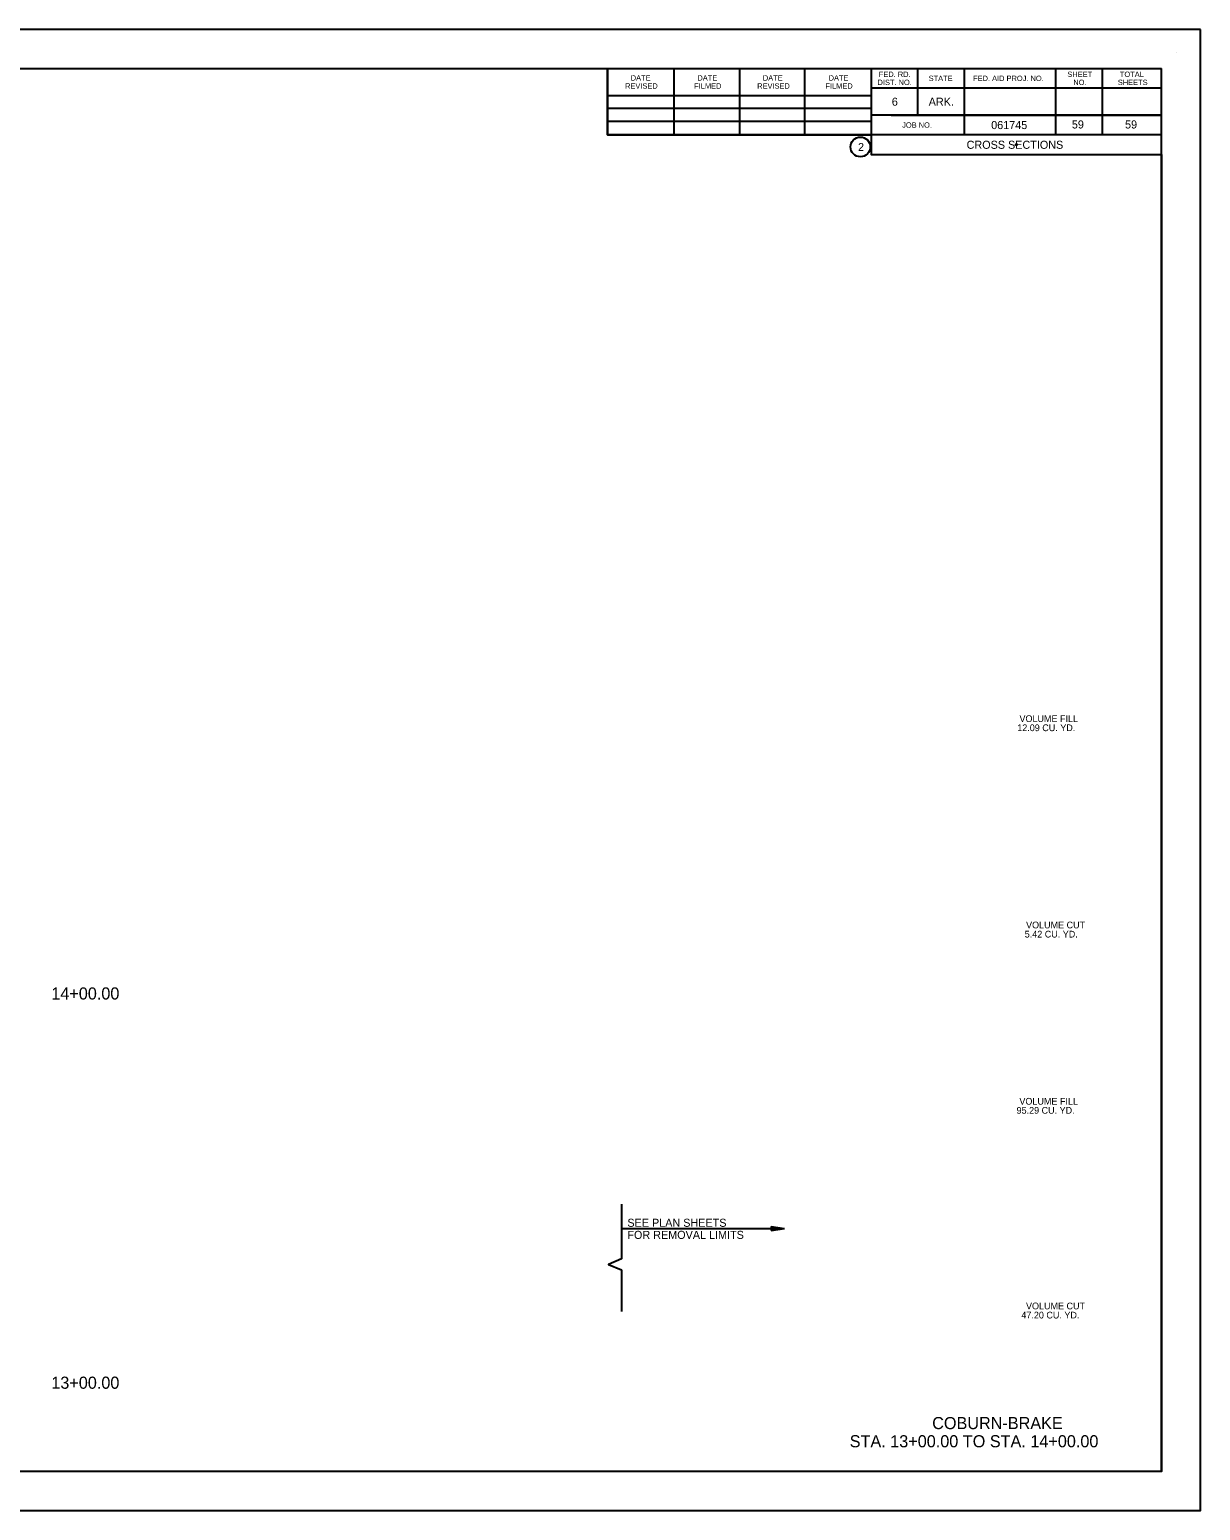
# Model space of a CAD drawing. Extents: x 1284907 to 1285667, y 403630 to 403851.
# Drawn here: x 1285493.5 to 1285667.4, y 403630.2 to 403850.2 of the extents above; entities that cross this region are included whole.
import ezdxf

# ---------------------------------------------------------------- set-up
doc = ezdxf.new("R2010")
doc.units = 0
for name, color, linetype in [('1', 7, 'Continuous'), ('Default', 7, 'Continuous'), ('NO PLOT CELL', 7, 'Continuous'), ('R_Draft', 7, 'Continuous'), ('R_Grid_Sta', 7, 'Continuous'), ('R_Vert Alg Annot_Drive', 7, 'Continuous')]:
    doc.layers.add(name, color=color, linetype=linetype)

msp = doc.modelspace()

# ---------------------------------------------------------------- linework, layer by layer
at = {"layer": '1'}
for p, q in [((1285663.82, 403846.78), (1285663.82, 403846.78)), ((1285342.56, 403844.47), (1285661.63, 403844.47)), ((1285579.37, 403834.59), (1285579.37, 403844.47)), ((1285589.23, 403834.59), (1285589.23, 403844.27)), ((1285598.99, 403834.59), (1285598.99, 403844.27)), ((1285608.67, 403834.59), (1285608.67, 403844.27)), ((1285618.53, 403844.47), (1285618.53, 403831.67)), ((1285625.37, 403844.47), (1285625.37, 403837.53)), ((1285632.31, 403844.47), (1285632.31, 403834.59)), ((1285645.89, 403844.47), (1285645.89, 403834.59)), ((1285652.83, 403844.47), (1285652.83, 403834.59)), ((1285661.63, 403636.01), (1285661.63, 403844.47)), ((1285661.63, 403841.53), (1285618.53, 403841.53)), ((1285661.63, 403841.55), (1285661.63, 403841.55)), ((1285579.37, 403840.45), (1285618.53, 403840.45)), ((1285579.37, 403838.59), (1285618.53, 403838.59)), ((1285579.37, 403834.59), (1285579.37, 403836.65)), ((1285579.37, 403836.65), (1285618.53, 403836.65)), ((1285661.63, 403837.53), (1285618.53, 403837.53)), ((1285621.49, 403837.53), (1285661.63, 403837.53)), ((1285661.63, 403834.59), (1285579.37, 403834.59)), ((1285618.53, 403831.67), (1285661.63, 403831.67)), ((1285661.63, 403636.01), (1285342.56, 403636.01))]:
    msp.add_line(p, q, dxfattribs=at)
for points in [[(1285667.4, 403850.24), (1285327.4, 403850.24), (1285327.4, 403630.24), (1285667.4, 403630.24)], [(1285342.56, 403636.01), (1285342.56, 403844.47), (1285579.37, 403844.47), (1285579.37, 403834.59), (1285618.53, 403834.59), (1285618.53, 403831.67), (1285661.63, 403831.67), (1285661.63, 403636.01)]]:
    msp.add_lwpolyline(points, close=True, dxfattribs=at)
msp.add_circle((1285616.91, 403832.81), 1.47, dxfattribs=at)
at = {"layer": 'NO PLOT CELL'}
msp.add_circle((1285640.08, 403833.13), 0.1, dxfattribs=at)
at = {"layer": 'R_Draft'}
for p, q in [((1285603.64, 403672.44), (1285605.64, 403672.14)), ((1285603.64, 403672.44), (1285603.64, 403671.84)), ((1285603.64, 403672.39), (1285605.31, 403672.14)), ((1285603.64, 403672.34), (1285604.96, 403672.14)), ((1285603.64, 403672.29), (1285604.63, 403672.14)), ((1285603.64, 403672.24), (1285604.29, 403672.14)), ((1285603.64, 403672.19), (1285603.96, 403672.14)), ((1285603.64, 403671.84), (1285605.64, 403672.14)), ((1285603.64, 403672.04), (1285604.29, 403672.14)), ((1285603.64, 403671.94), (1285604.96, 403672.14)), ((1285603.64, 403671.89), (1285605.31, 403672.14)), ((1285603.64, 403671.99), (1285604.63, 403672.14)), ((1285603.64, 403672.1), (1285603.96, 403672.14)), ((1285581.43, 403665.98), (1285581.43, 403659.78))]:
    msp.add_line(p, q, dxfattribs=at)
msp.add_lwpolyline([(1285581.43, 403675.74), (1285581.43, 403667.6), (1285579.52, 403666.76), (1285581.43, 403665.98)], dxfattribs=at)
at = {"layer": 'R_Vert Alg Annot_Drive'}
msp.add_line((1285581.43, 403672.14), (1285605.64, 403672.14), dxfattribs=at)

# ---------------------------------------------------------------- texts
at = {"layer": '1'}
for s, height, p in [('DATE', 0.8, (1285582.8, 403842.66)), ('DATE', 0.8, (1285592.7, 403842.66)), ('DATE', 0.8, (1285602.42, 403842.66)), ('DATE', 0.8, (1285612.19, 403842.66)), ('FED. RD.', 0.8, (1285619.64, 403843.2)), ('STATE', 0.8, (1285627.04, 403842.6)), ('FED. AID PROJ. NO.', 0.8, (1285633.64, 403842.6)), ('SHEET', 0.8, (1285647.64, 403843.2)), ('TOTAL', 0.8, (1285655.44, 403843.2)), ('REVISED', 0.8, (1285581.96, 403841.46)), ('FILMED', 0.8, (1285592.22, 403841.46)), ('REVISED', 0.8, (1285601.58, 403841.46)), ('FILMED', 0.8, (1285611.71, 403841.46)), ('DIST. NO.', 0.8, (1285619.45, 403842)), ('NO.', 0.8, (1285648.53, 403842)), ('SHEETS', 0.8, (1285655.14, 403842)), ('6', 1.2, (1285621.57, 403838.93)), ('6', 1.2, (1285621.57, 403838.93)), ('ARK.', 1.2, (1285627.05, 403838.93)), ('JOB NO.', 0.8, (1285623.11, 403835.66)), ('061745', 1.2, (1285636.33, 403835.46)), ('59', 1.2, (1285648.31, 403835.55)), ('59', 1.2, (1285656.21, 403835.55)), ('2', 1.17, (1285616.57, 403832.22)), ('CROSS SECTIONS', 1.2, (1285632.68, 403832.53))]:
    msp.add_text(s, height=height, dxfattribs=at).set_placement(p)
at = {"layer": 'Default'}
for s, p in [('12.09 CU. YD.', (1285640.2, 403746.01)), ('VOLUME FILL', (1285640.53, 403747.37)), ('VOLUME CUT', (1285641.51, 403716.71)), ('5.42 CU. YD.', (1285641.31, 403715.35)), ('VOLUME FILL', (1285640.52, 403690.52)), ('95.29 CU. YD.', (1285640.1, 403689.17)), ('VOLUME CUT', (1285641.5, 403660.11)), ('47.20 CU. YD.', (1285640.81, 403658.75))]:
    msp.add_text(s, height=1, dxfattribs=at).set_placement(p)
at = {"layer": 'R_Grid_Sta'}
for s, p in [('14+00.00', (1285496.75, 403706.14)), ('13+00.00', (1285496.75, 403648.31)), ('COBURN-BRAKE', (1285627.57, 403642.31)), ('STA. 13+00.00 TO STA. 14+00.00', (1285615.32, 403639.61))]:
    msp.add_text(s, height=1.8, dxfattribs=at).set_placement(p)
at = {"layer": 'R_Vert Alg Annot_Drive'}
for s, p in [('SEE PLAN SHEETS ', (1285582.3, 403672.37)), ('FOR REMOVAL LIMITS', (1285582.3, 403670.57))]:
    msp.add_text(s, height=1.2, dxfattribs=at).set_placement(p)

doc.saveas('drawing.dxf')
